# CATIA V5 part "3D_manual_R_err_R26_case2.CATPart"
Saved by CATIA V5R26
Part number: 3D_manual_R_err
Description: Copyright©3D-raku.com  Copyright©CATIAmaster.xyz
Bounding box of the stored display mesh (mm): x 36.39 to 126.419, y -15.123 to 37.571, z -20 to 13
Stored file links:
  F:\Dropbox\ina-catia_web\CATIA-master\CATIAデータ\3D_manual_R_err\3D_manual_R_err_R26_case2.CATPart
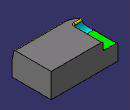
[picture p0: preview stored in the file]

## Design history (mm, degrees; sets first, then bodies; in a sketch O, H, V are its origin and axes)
Body1
  Sketch1 on xy-plane, origin (0, 0, 0), H (1, 0, 0), V (0, 1, 0)
    line L1 (36.3899, 37.5714) -> (126.4194, 37.5714)
    line L2 (126.4194, 37.5714) -> (126.4194, -15.1231)
    line L3 (126.4194, -15.1231) -> (59.1167, -15.1231)
    line L4 (36.3899, 7.6038) -> (36.3899, 37.5714)
    arc A1 centre (59.1167, 7.6038) radius 22.7269 from (59.1167, -15.1231) to (36.3899, 7.6038) cw
    radius A1 = 22.7269
    horizontal: L1 H, L3 H
    vertical: L2 V, L4 V
    tangency: A1 L3, A1 L4
  Pad1: profile Sketch1, direction (0, 0, -1), length 20, opposite side length 13
  Draft1: Angle 11, Neutral xy-plane, PullDir xy-plane, SupportToDraft face of Pad1 from Sketch1.L3
  Fillet1: radius 3, on edge [face of Pad1 from Sketch1.A1 | face of Pad1 from Sketch1.A1]
  Body2
    Sketch2 on xy-plane, origin (0, 0, 0), H (1, 0, 0), V (0, 1, 0)
      line L1 (18.6626, 44.6458) -> (56.3899, 44.6458)
      line L2 (56.3899, 44.6458) -> (56.3899, -2.1231)
      line L3 (56.3899, -2.1231) -> (18.6626, -2.1231)
      line L4 (18.6626, -2.1231) -> (18.6626, 44.6458)
      reference projected line E1 (59.1167, -15.1231) -> (126.4194, -15.1231) from Sketch1.L3
      reference projected line E2 (36.3899, 37.5714) -> (36.3899, 7.6038) from Sketch1.L4
      distance E1 L3 = 13
      distance L2 E2 = 20
      horizontal: L1 H, L3 H
      vertical: L2 V, L4 V
    Pad2: profile Sketch2, direction (0, 0, 1), length 20, opposite side length -2
  Remove1: tool Body2
  Fillet2: radius 9, on edge [face of Pad2 from Sketch2.L3 | start face of Pad2]
  Fillet3: radius 2, on edge [face of Fillet2 | face of Pad1 from Sketch1.A1]
  Fillet4: radius 2, on edge [face of Pad2 from Sketch2.L2 | start face of Pad2]
  Fillet5: radius 2, on edge [start face of Pad1 | face of Pad2 from Sketch2.L2]
Body3 (main body)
